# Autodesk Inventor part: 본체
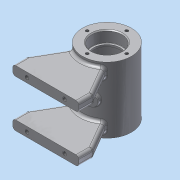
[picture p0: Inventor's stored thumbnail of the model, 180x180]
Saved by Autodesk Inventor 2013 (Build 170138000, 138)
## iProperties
Created: 2018-05
Part Number: 본체
Material: 알루미늄 6061
Document SubType Name: Modeling
Designer: dgall
Density: 2.71 g/cm^3
Mass: 318.856 g
Surface Area: 375.823 cm^2
Volume: 117.659 cm^3
Author: dgall
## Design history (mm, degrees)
sketch "스케치1"
  geometry: C1 r 26 at (0, 0); 1 further point
  constraints: 1 centre point, 1 coincident
  dimensions: "d0" = 52 diameter of C1
extrude "돌출1" new body sketch "스케치1" distance "d1" = 70; taper "d2" = 0 deg
sketch "스케치2"
  geometry: L1 (26, 70)-(26, 0) reference; L2 (26, 0)-(-26, 0) reference; L3 (-26, 0)-(-26, 70) reference; L4 (-26, 70)-(26, 70) reference; L5 (0, 0)-(0, 70); L6 (16, 70)-(16, 58.3); L7 (15.7, 58)-(14, 58); L8 (14, 58)-(14, 56); L9 (14, 56)-(18, 56); L10 (21, 53)-(21, 17); L11 (18, 14)-(14, 14); L12 (14, 14)-(14, 12); L13 (14, 12)-(15.7, 12); L14 (16, 11.7)-(16, 0); L15 (16, 70)-(0, 70); L16 (16, 0)-(0, 0); A1 r 3 centre (18, 53) between (21, 53) and (18, 56); A2 r 3 centre (18, 17) between (18, 14) and (21, 17); A3 r 0.3 centre (15.7, 58.3) between (15.7, 58) and (16, 58.3); A4 r 0.3 centre (15.7, 11.7) between (16, 11.7) and (15.7, 12); 2 further points
  constraints: 24 end point, 8 point on circle, 8 tangent, 7 parallel, 6 point on line, 4 centre point, 3 collinear, 2 equal radius, 1 midpoint, 1 perpendicular
  dimensions: "d3" = 28 diameter of L8 L5; "d5" = 28 diameter of L12 L5; "d6" = 32 diameter of L6 L5; "d7" = 32 diameter of L14 L5; "d8" = 42 diameter of L10 L5; "d9" = 2 distance of L7.end L8.end; "d10" = 2 distance of L11.end L12.end; "d11" = 12 distance of L6.start point (16, 58); "d12" = 12 distance of point (16, 12) L14.end; "d13" = 3 radius of A1; "d14" = 0.3 radius of A3
revolve "회전1" sketch "스케치2" stored, may be unused: angle "d15" = 90 deg
chamfer "모따기1" distance "d16" = 1; stored, may be unused: second distance "d17" = 2, angle "d18" = 45 deg
node "작업 평면1"
node "작업 평면2"
sketch "스케치3"
  geometry: L1 (-35, -65)-(35, -65); L2 (-35, -65)-(-35, -50); L3 (-35, -50)-(-17.325, -19.386); L4 (35, -65)-(35, -50); L5 (35, -50)-(17.325, -19.386); C1 r 20.236 at (0, 0) reference; A1 r 26 centre (0, 0) between (-17.325, -19.386) and (17.325, -19.386) reference; 2 further points
  constraints: 10 end point, 2 point on circle, 1 horizontal, 1 midpoint, 1 parallel, 1 perpendicular, 1 vertical alignment
  dimensions: "d20" = 70 distance of L1.start L1.end; "d21" = 65 distance of point (0, 0) point (0, -65); "d22" = 15 distance of L1.start L2.end; "d23" = 15 distance of L1.end L4.end; "d24" = 30 deg angle of L4 L5; "d25" = 30 deg angle of L2 L3
extrude "돌출2" join sketch "스케치3" distance "d26" = 10; taper "d27" = 0 deg
fillet "모깎기1" dims "d28" = 3
fillet "모깎기2" dims "d29" = 3
node "작업 평면3"
sketch "스케치4"
  geometry: L1 (-35, -65)-(35, -65); L2 (-35, -65)-(-35, -50); L3 (-35, -50)-(-17.325, -19.386); L4 (35, -65)-(35, -50); L5 (35, -50)-(17.325, -19.386); C1 r 20.236 at (0, 0) reference; A1 r 26 centre (0, 0) between (-17.325, -19.386) and (17.325, -19.386) reference; 2 further points
  constraints: 10 end point, 2 point on circle, 1 horizontal, 1 midpoint, 1 parallel, 1 perpendicular, 1 vertical alignment
  dimensions: "d31" = 70 distance of L1.start L1.end; "d32" = 65 distance of point (0, -65) point (0, 0); "d33" = 15 distance of L1.start L2.end; "d34" = 15 distance of L1.end L4.end; "d35" = 30 deg angle of L2 L3; "d36" = 30 deg angle of L4 L5
extrude "돌출3" join sketch "스케치4" distance "d37" = 10; taper "d38" = 0 deg
fillet "모깎기3" dims "d39" = 3
fillet "모깎기4" dims "d40" = 3
fillet "모깎기5" dims "d41" = 3
fillet "모깎기6" dims "d42" = 3
node "작업 평면5"
  node "작업 평면4"
sketch "스케치5"
  geometry: L1 (26, 70)-(-26, 70) reference; C1 r 5 at (0, 35); 2 further points
  constraints: 1 centre point, 1 coincident, 1 vertical alignment
  dimensions: "d44" = 35 distance from line of point (0, 35) L1; "d45" = 10 diameter of C1
extrude "돌출4" join sketch "스케치5" stored distance "d46" = 10; taper "d47" = 0 deg
fillet "모깎기7" dims "d48" = 2
sketch "스케치6"
  geometry: C1 r 5 at (0, 0) reference; 1 further point
hole "구멍1" sketch "스케치6" at (0, 0) diameter "d49" = 5.188; stored, may be unused: countersink angle "d53" = 90 deg, drill point angle "d55" = 118 deg; dims "d50" = 6, "d51" = 4, "d52" = 2, "d54" = 8
sketch "스케치7"
  geometry: L1 (67, -43)-(67, -47) reference; 3 further points
  constraints: 1 horizontal alignment, 1 midpoint
  dimensions: "d56" = 20 horizontal distance of point (32, -55) point (52, -45)
hole "구멍2" sketch "스케치7" at (52, -45) diameter "d57" = 4.134; stored, may be unused: countersink angle "d61" = 90 deg, drill point angle "d63" = 118 deg; dims "d58" = 8, "d59" = 4, "d60" = 2, "d62" = 10
node "작업 평면6"
sketch "스케치8" dims "d64" = 42
  geometry: C1 r 17 at (0, 0) reference; 2 further points
  constraints: 2 vertical alignment, 1 coincident, 2 other
hole "구멍3" sketch "스케치8" at (0, 21) diameter "d65" = 3.242; stored, may be unused: countersink angle "d69" = 90 deg, drill point angle "d71" = 118 deg; dims "d66" = 8, "d67" = 4, "d68" = 2, "d70" = 10
sketch "스케치9"
  geometry: L1 (-17, 70)-(-16, 69) reference; L2 (-16, 69)-(-16, 58.3) reference; L3 (-15.7, 58)-(-14, 58) reference; L4 (-14, 58)-(-14, 56) reference; L5 (-14, 56)-(-18, 56) reference; L6 (-21, 53)-(-21, 17) reference; L7 (-18, 14)-(-14, 14) reference; L8 (-14, 14)-(-14, 12) reference; L9 (-14, 12)-(-15.7, 12) reference; L10 (-16, 11.7)-(-16, 1) reference; L11 (-16, 1)-(-17, 0) reference; L12 (-17, 0)-(-19.379, 0) reference; L13 (-19.379, 0)-(-19.379, 10) reference; L14 (-19.379, 10)-(-21, 10.974) reference; L15 (-21, 10.974)-(-22.621, 10) reference; L16 (-22.621, 10)-(-22.621, 0) reference; L17 (-22.621, 0)-(-26, 0) reference; L18 (-26, 0)-(-26, 70) reference; L19 (-26, 70)-(-22.621, 70) reference; L20 (-22.621, 70)-(-22.621, 60) reference; L21 (-22.621, 60)-(-21, 59.026) reference; L22 (-21, 59.026)-(-19.379, 60) reference; L23 (-19.379, 60)-(-19.379, 70) reference; L24 (-19.379, 70)-(-17, 70) reference; L25 (16, 69)-(17, 70) reference; L26 (17, 70)-(19.379, 70) reference; L27 (19.379, 70)-(19.379, 60) reference; L28 (19.379, 60)-(21, 59.026) reference; L29 (21, 59.026)-(22.621, 60) reference; L30 (22.621, 60)-(22.621, 70) reference; L31 (22.621, 70)-(26, 70) reference; L32 (26, 70)-(26, 0) reference; L33 (26, 0)-(22.621, 0) reference; L34 (22.621, 0)-(22.621, 10) reference; L35 (22.621, 10)-(21, 10.974) reference; L36 (21, 10.974)-(19.379, 10) reference; L37 (19.379, 10)-(19.379, 0) reference; L38 (19.379, 0)-(17, 0) reference; L39 (17, 0)-(16, 1) reference; L40 (16, 1)-(16, 11.7) reference; L41 (15.7, 12)-(14, 12) reference; L42 (14, 12)-(14, 14) reference; L43 (14, 14)-(18, 14) reference; L44 (21, 17)-(21, 53) reference; L45 (18, 56)-(14, 56) reference; L46 (14, 56)-(14, 58) reference; L47 (14, 58)-(15.7, 58) reference; L48 (16, 58.3)-(16, 69) reference; C1 r 6 at (0, 35); A1 r 0.3 centre (-15.7, 58.3) between (-16, 58.3) and (-15.7, 58) reference; A2 r 3 centre (-18, 53) between (-18, 56) and (-21, 53) reference; A3 r 3 centre (-18, 17) between (-21, 17) and (-18, 14) reference; A4 r 0.3 centre (-15.7, 11.7) between (-15.7, 12) and (-16, 11.7) reference; A5 r 0.3 centre (15.7, 11.7) between (16, 11.7) and (15.7, 12) reference; A6 r 3 centre (18, 17) between (18, 14) and (21, 17) reference; A7 r 3 centre (18, 53) between (21, 53) and (18, 56) reference; A8 r 0.3 centre (15.7, 58.3) between (15.7, 58) and (16, 58.3) reference; 1 further point
  constraints: 1 centre point, 1 vertical alignment
  dimensions: "d75" = 12 diameter of C1; "d76" = 35 distance of point (0, 0) C1.centre
  node "절단 모서리 투영4"
sketch "스케치10"
  geometry: L1 (-5, 27.111)-(-5, 29) reference; L2 (-5, 29)-(-2.594, 29) reference; L3 (-2.594, 29)-(-2.594, 20.839) reference; L4 (2.594, 20.839)-(2.594, 29) reference; L5 (2.594, 29)-(5, 29) reference; L6 (5, 29)-(5, 27.111) reference; L7 (-32, -65)-(32, -65) reference; L8 (0, 0)-(0, -65); L9 (0, 0)-(9.919, -27.251); L10 (9.919, -27.251)-(4.28, -29.303); L11 (4.28, -29.303)-(3.014, -25.825); A1 r 26 centre (0, 0) between (-6.5, 25.174) and (6.5, 25.174) reference; A2 r 21 centre (0, 0) between (-2.594, 20.839) and (2.594, 20.839) reference; A3 r 26 centre (0, 0) between (6.5, 25.174) and (-6.5, 25.174); A4 r 26 centre (0, 0) between (3.014, -25.825) and (8.893, -24.432); 1 further point
  constraints: 8 end point, 5 point on circle, 2 centre point, 2 perpendicular, 1 coincident, 1 midpoint, 1 point on line, 4 other
  dimensions: "d77" = 20 deg angle of L8 L9; "d78" = 29 distance of L9.end point (0, 0); "d82" = 6 distance between parallel lines of L11 L9
  node "절단 모서리 투영5"
node "작업 평면7"
sketch "스케치11"
  geometry: L1 (25.081, 23)-(25.081, 27) reference; C1 r 6 at (0, 0); 1 further point
  constraints: 1 centre point
  dimensions: "d79" = 12 diameter of C1; "d80" = 25.08142 distance from line of L1 C1.centre; "d81" = 35 vertical distance of point (-9.919, -35) C1.centre
revolve "회전2" stored, may be unused: angle "d83" = 90 deg
fillet "모깎기8" dims "d84" = 2
sketch "스케치12"
  geometry: C1 r 6 at (0, 0) reference; 1 further point
hole "구멍4" sketch "스케치12" at (0, 0) diameter "d85" = 5.188; stored, may be unused: countersink angle "d89" = 90 deg, drill point angle "d91" = 118 deg; dims "d86" = 8, "d87" = 4, "d88" = 2, "d90" = 10
node "작업 평면8"
sketch "스케치13"
  geometry: L1 (-26, 0)-(26, 0) reference; L2 (-26, 0)-(-26, 70) reference; 2 further points
  constraints: 1 other
  dimensions: "d92" = 35 distance from line of point (0, 35) L1; "d93" = 26 distance from line of L2 point (0, 35)
feature "엠보싱1" sketch "스케치13" dims "d0" = 52, "d94" = 0.5, "d95" = 0
node "솔리드1"
mirror "대칭1"
mirror "대칭2"
pattern_circular "원형 패턴1" dims angle "d73" = 360 deg
mirror "대칭3"
node "절단 모서리 투영1"
node "절단 모서리 투영2"
node "절단 모서리 투영3"
other parameters: "d43" = 3
